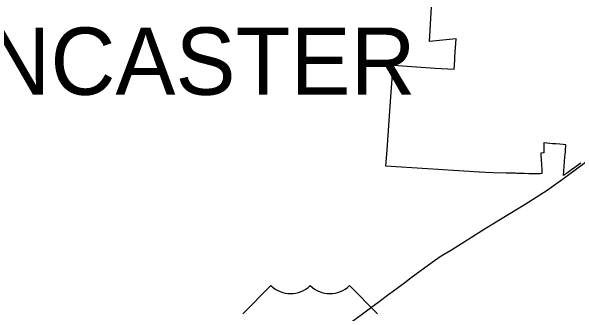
# Model space of a CAD drawing. Extents: x 1801177 to 2073177, y 551183 to 727183.
# Drawn here: x 1923389 to 1932810, y 618422 to 623455 of the extents above; entities that cross this region are included whole.
import ezdxf

# ---------------------------------------------------------------- set-up
doc = ezdxf.new("R2010")
doc.units = 0
for name, color, linetype in [('GM_X_Corporation', 7, 'Continuous'), ('GM_X_Corporation_Text', 7, 'Continuous'), ('GM_X_US_Route', 7, 'Continuous'), ('GM_X_US_Shield', 7, 'Continuous')]:
    doc.layers.add(name, color=color, linetype=linetype)

msp = doc.modelspace()

# ---------------------------------------------------------------- linework, layer by layer
at = {"layer": 'GM_X_Corporation'}
msp.add_lwpolyline([(1932860.8, 620927), (1932784.7, 620872.4), (1932740.6, 620840.7), (1932728.3, 620831.1), (1932685.2, 620797.7), (1932641, 620767.2), (1932576, 620722.5), (1932598.5, 621035.3), (1932599, 621041.6), (1932600.7, 621065.6), (1932605.1, 621126), (1932606.5, 621146), (1932611.9, 621221.4), (1932612.7, 621232.6), (1932568.2, 621236.3), (1932512.4, 621241), (1932444.8, 621246.6), (1932389.2, 621251.2), (1932349.6, 621254.5), (1932245.3, 621263.2), (1932246, 621208.4), (1932246.1, 621197.1), (1932247.3, 621098.4), (1932197.5, 621094.6), (1932199.7, 621054.5), (1932202.9, 620996.6), (1932208.5, 620895.3), (1932212.4, 620826.5), (1932216.4, 620755.3), (1932188.3, 620747.1), (1932184.5, 620747.2), (1932180.7, 620747.3), (1932095.6, 620749.6), (1932000.9, 620752.3), (1931996.4, 620752.4), (1931925.5, 620754.4), (1931924.3, 620754.4), (1931880.4, 620755.6), (1931835.4, 620756.9), (1931800, 620757.8), (1931796.4, 620757.9), (1931775.6, 620758.5), (1931715.4, 620760.2), (1931689.4, 620760.9), (1931619.4, 620762.8), (1931405.3, 620768.8), (1931271.8, 620772.5), (1931176.8, 620775.1), (1931171.3, 620775.2), (1931002.8, 620786.3), (1929618.6, 620877.3), (1929623.6, 620944.3), (1929638.8, 621150.2), (1929692.6, 621877.1), (1929741.8, 622557), (1930439.2, 622511.4), (1930754.5, 622491.2), (1930765.6, 622643.3), (1930769.4, 622695.2), (1930791.5, 622995.1), (1930344.5, 622950.4), (1930378.2, 623523)], dxfattribs=at)
at = {"layer": 'GM_X_US_Route'}
msp.add_line((1929483.5, 618607.5), (1929689.2, 618760.4), dxfattribs=at)
for points in [[(1932555.4, 620660.2), (1932638.7, 620719.8), (1932919.5, 620926.8), (1933079.4, 621040.7), (1933310.2, 621198.1), (1933697.1, 621481.6), (1933973.7, 621673.6), (1934411.5, 621993.5), (1934590.5, 622125.1)], [(1930019.2, 619004.6), (1930206.4, 619144.7), (1930431, 619309.5), (1930539.9, 619382.3), (1930709.5, 619482.8), (1931272.3, 619839.2), (1931934.3, 620243.4), (1932301.6, 620478.5), (1932555.4, 620660.2)], [(1929689.2, 618760.4), (1929722.1, 618784.8), (1929956.8, 618957.9), (1930019.2, 619004.6)], [(1928541.1, 617903.3), (1928904.3, 618174.6), (1929087.7, 618313), (1929207, 618401.5), (1929364.5, 618517.7), (1929444.8, 618578.1), (1929483.5, 618607.5)]]:
    msp.add_lwpolyline(points, dxfattribs=at)
at = {"layer": 'GM_X_US_Shield'}
for p, q in [((1927707.7, 618888.6), (1927240.7, 618421.6)), ((1929482.2, 618421.6), (1929015.2, 618888.6))]:
    msp.add_line(p, q, dxfattribs=at)
for centre in [(1928034.6, 619222.1), (1928688.3, 619222.1)]:
    msp.add_arc(centre, 467, 225.573, 314.427, dxfattribs=at)

# ---------------------------------------------------------------- texts
at = {"layer": 'GM_X_Corporation_Text'}
msp.add_text('LANCASTER', height=1120, rotation=0.00001, dxfattribs=at).set_placement((1921126, 622065.7))

doc.saveas('drawing.dxf')
